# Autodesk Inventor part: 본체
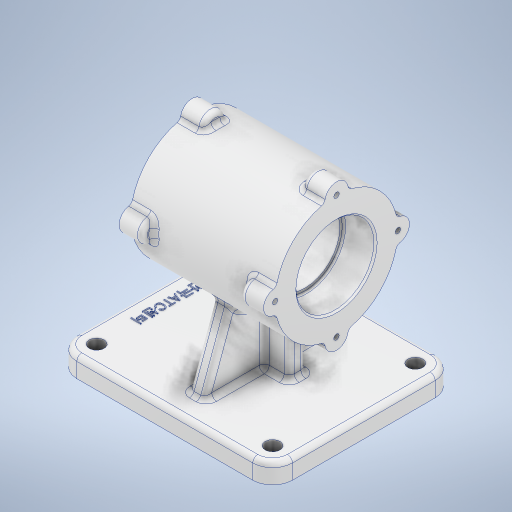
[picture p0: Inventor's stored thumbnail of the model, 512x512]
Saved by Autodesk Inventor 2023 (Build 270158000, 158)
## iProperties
Created: 2023-08
Part Number: 본체
Material: 알루미늄 6061
Document SubType Name: Modeling
Designer: asung
Mass: 1215.23 g
Surface Area: 797.345 cm^2
Volume: 450.085 cm^3
Density: 2.7 g/cm^3
Appearance: 알루미늄 - 평지
Author: asung
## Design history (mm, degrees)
sketch "스케치1"
  geometry: L1 (53, -55)-(-53, -55); L2 (-65, -43)-(-65, 43); L3 (-53, 55)-(53, 55); L4 (65, 43)-(65, -43); L5 (65, -55)-(-65, 55); L6 (-65, -55)-(65, 55); C1 r 4.5 at (53, -43); C2 r 4.5 at (-53, -43); C3 r 4.5 at (53, 43); C4 r 4.5 at (-53, 43); A1 r 12 centre (53, -43) between (53, -55) and (65, -43); A2 r 12 centre (-53, -43) between (-65, -43) and (-53, -55); A3 r 12 centre (-53, 43) between (-53, 55) and (-65, 43); A4 r 12 centre (53, 43) between (65, 43) and (53, 55); 1 further point
  constraints: 12 end point, 8 centre point, 8 point on circle, 8 point on line, 8 tangent, 4 coincident, 3 equal radius, 2 midpoint, 2 parallel, 1 horizontal, 1 perpendicular
  dimensions: "d0" = 130 distance of L5.end L6.end; "d1" = 110 distance of L6.start L5.end; "d2" = 12 radius of A1; "d3" = 9 diameter of C1; "d4" = 9 diameter of C2; "d5" = 9 diameter of C3; "d6" = 9 diameter of C4
extrude "돌출1" new body sketch "스케치1" distance "d7" = 12; taper "d8" = 0 deg
node "작업 평면1"
sketch "스케치2"
  geometry: L1 (43, 0)-(43, 82); C1 r 37 at (43, 82)
  constraints: 2 end point, 1 centre point, 1 coincident, 1 vertical
  dimensions: "d10" = 82 distance of L1.start L1.end; "d11" = 37 radius of C1
extrude "돌출2" join sketch "스케치2" stored distance "d12" = 87; taper "d13" = 0 deg
sketch "스케치3"
  geometry: C1 r 7 at (0, 37); 2 further points
  constraints: 1 centre point, 1 vertical alignment, 1 other
  dimensions: "d14" = 7 radius of C1
extrude "돌출3" join sketch "스케치3" distance "d15" = 14; taper "d16" = 0 deg
sketch "스케치4"
  geometry: A1 r 7 centre (43, 119) between (49.969, 118.338) and (36.031, 118.338) reference; 2 further points
  constraints: 1 coincident
hole "구멍1" sketch "스케치4" at (43, 119) diameter "d17" = 3.242; stored, may be unused: countersink angle "d21" = 90 deg, drill point angle "d23" = 118 deg; dims "d18" = 8, "d19" = 4, "d20" = 2, "d22" = 10
fillet "모깎기1" dims "d24" = 3
fillet "모깎기2" dims "d25" = 3
sketch "스케치5"
  geometry: A1 r 37 centre (43, 82) between (78.863, 91.104) and (52.104, 117.863) reference; 2 further points
  constraints: 1 coincident
hole "구멍2" sketch "스케치5" at (43, 82) diameter "d29" = 42; stored, may be unused: countersink angle "d33" = 90 deg, drill point angle "d35" = 0 deg; dims "d30" = 8, "d31" = 47, "d32" = 19, "d34" = 87
sketch "스케치6"
  geometry: C1 r 37 at (0, 0) reference; 2 further points
  constraints: 1 coincident
hole "구멍3" sketch "스케치6" at (0, 0) diameter "d36" = 42; stored, may be unused: countersink angle "d40" = 90 deg, drill point angle "d42" = 0 deg; dims "d37" = 6, "d38" = 47, "d39" = 19, "d41" = 87
chamfer "모따기1" distance "d43" = 1; stored, may be unused: second distance "d44" = 2, angle "d45" = 45 deg
fillet "모깎기3" dims "d46" = 1
sketch "스케치7"
  geometry: L1 (-15, 5)-(25, 5); L2 (25, 5)-(25, -5); L3 (25, -5)-(-15, -5); L4 (-15, -5)-(-15, 5); L5 (-65, 43)-(-65, -43) reference; L6 (-53, -38.5)-(-53, -47.5); L7 (53, 55)-(-53, 55) reference; A1 r 4.5 centre (-53, -43) between (-53, -38.5) and (-53, -47.5) reference; 3 further points
  constraints: 10 end point, 2 midpoint, 2 parallel, 2 point on circle, 1 horizontal, 1 perpendicular, 1 vertical
  dimensions: "d47" = 10 distance of L2.end L1.end; "d48" = 40 distance of L1.start L1.end; "d49" = 70 distance from line of L5 point (5, -5); "d50" = 58 horizontal distance of L6.end point (5, -5); "d51" = 55 distance from line of point (25, 0) L7
extrude "돌출4" join sketch "스케치7" stored distance "d52" = 14; taper "d53" = 0 deg
sketch "스케치8"
  geometry: L1 (98, 12)-(98, 0) reference; L2 (98, 0)-(-12, 0) reference; L3 (-12, 0)-(-12, 12) reference; L4 (-12, 12)-(38, 12) reference; L5 (38, 12)-(38, 45.339) reference; L6 (48, 45.339)-(48, 12) reference; L7 (48, 12)-(98, 12) reference; L8 (2, 12)-(17.664, 55.036); L9 (86, 12)-(0, 12) reference; L10 (84, 12)-(68.336, 55.036); C1 r 21 at (43, 82) reference; A1 r 37 centre (43, 82) between (48, 45.339) and (38, 45.339) reference; 1 further point
  constraints: 4 end point, 2 point on circle, 2 point on line
  dimensions: "d54" = 14 distance from line of L1 L10.start; "d55" = 14 distance from line of L3 L8.start; "d56" = 110 deg angle of L7 L10; "d57" = 110 deg angle of L4 L8
  node "절단 모서리 투영1"
feature "리브1" dims "d58" = 1, "d59" = 10, "d60" = 0, "d61" = 0, "d62" = 1, "d63" = 1
feature "리브2" dims "d64" = 1, "d65" = 10, "d66" = 0, "d67" = 0, "d68" = 1, "d69" = 1
fillet "모깎기4" dims "d70" = 3
fillet "모깎기5" dims "d71" = 3
fillet "모깎기6" dims "d72" = 3
sketch "스케치9"
  geometry: L1 (62, -43)-(62, 43) reference; L2 (53, 52)-(-53, 52) reference; L3 (-62, 43)-(-62, -43) reference; L4 (-53, -52)-(53, -52) reference; L5 (-12, -8)-(-3, -8) reference; L6 (-3, -8)-(-3, -36.716) reference; L7 (3, -43.101)-(7, -43.101) reference; L8 (13, -36.716)-(13, -8) reference; L9 (13, -8)-(22, -8) reference; L10 (28, -2)-(28, 2) reference; L11 (22, 8)-(13, 8) reference; L12 (13, 8)-(13, 36.716) reference; L13 (7, 43.101)-(3, 43.101) reference; L14 (-3, 36.716)-(-3, 8) reference; L15 (-3, 8)-(-12, 8) reference; L16 (-18, 2)-(-18, -2) reference; C1 r 4.5 at (-53, 43) reference; C2 r 4.5 at (53, 43) reference; C3 r 4.5 at (-53, -43) reference; C4 r 4.5 at (53, -43) reference; A1 r 9 centre (53, -43) between (53, -52) and (62, -43) reference; A2 r 9 centre (53, 43) between (62, 43) and (53, 52) reference; A3 r 9 centre (-53, 43) between (-53, 52) and (-62, 43) reference; A4 r 9 centre (-53, -43) between (-62, -43) and (-53, -52) reference; A5 r 6 centre (22, -2) between (22, -8) and (28, -2) reference; A6 r 6 centre (22, 2) between (28, 2) and (22, 8) reference; A7 r 6 centre (-12, 2) between (-12, 8) and (-18, 2) reference; A8 r 6 centre (-12, -2) between (-18, -2) and (-12, -8) reference; 2 further points
  constraints: 1 vertical alignment, 5 other
  dimensions: "d73" = 0 vertical distance of point (0, 0) point (-53, 0)
feature "엠보싱1" sketch "스케치9" dims "d0" = 130, "d1" = 110, "d2" = 12, "d3" = 9, "d4" = 9, "d5" = 9, "d6" = 9, "d74" = 0.5, "d75" = 0
node "솔리드1"
pattern_circular "원형 패턴1" dims "d27" = 360 deg
mirror "미러1"
node "절단 모서리 투영2"
feature "A9D066F2-1C7D-4E18-AEED-F7BC21143FA4" dims "d29" = 42, "d30" = 8, "d31" = 47, "d32" = 19, "d33" = 90 deg, "d34" = 87, "d35" = 0
